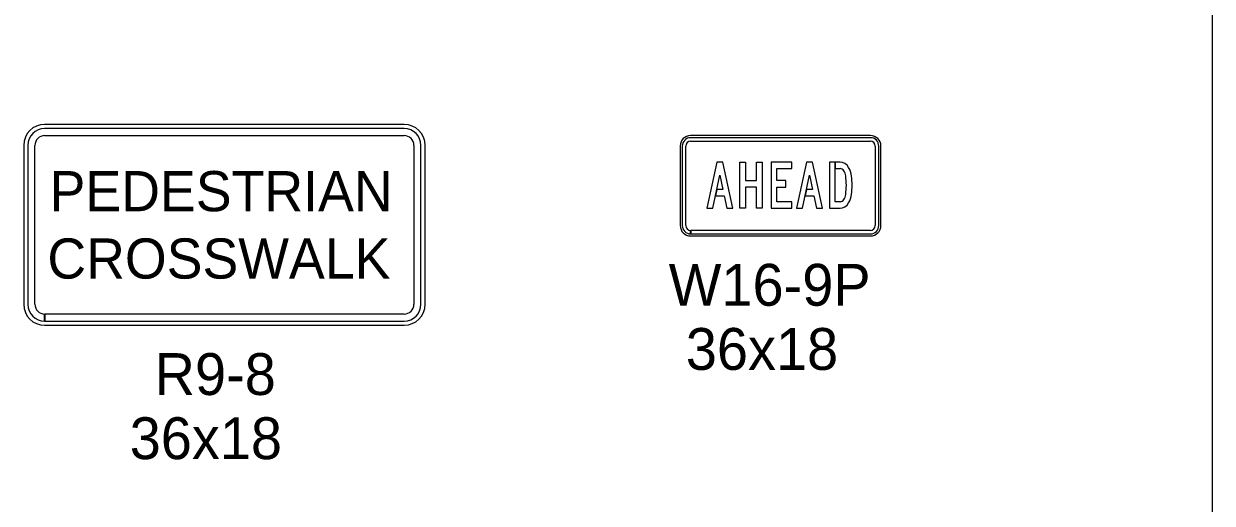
# Model space of a CAD drawing. Extents: x 1458 to 4498, y 17709 to 24109.
# Drawn here: x 2706.5 to 3132.7, y 20956.1 to 21127.9 of the extents above; entities that cross this region are included whole.
import ezdxf

# ---------------------------------------------------------------- set-up
doc = ezdxf.new("R2010")
doc.units = 0
for name, color, linetype in [('P_ODOT_PLAN_TBlock', 7, 'Continuous'), ('P_TRAF_SIGN_SignDetails', 7, 'Continuous'), ('P_TRAF_TCP_General', 7, 'Continuous')]:
    doc.layers.add(name, color=color, linetype=linetype)

msp = doc.modelspace()

# ---------------------------------------------------------------- linework, layer by layer
at = {"layer": 'P_ODOT_PLAN_TBlock'}
msp.add_line((3132.73, 21909.14), (3132.73, 20667.08), dxfattribs=at)
at = {"layer": 'P_TRAF_SIGN_SignDetails'}
for points in [[(2955.01, 21068.58), (2954.52, 21066.26), (2957.69, 21066.26), (2958.65, 21061.84), (2960.75, 21061.84), (2957.2, 21078.35), (2955.01, 21078.35), (2951.46, 21061.84), (2953.57, 21061.84), (2956.1, 21073.65), (2957.2, 21068.58)], [(2963.24, 21078.35), (2965.29, 21078.35), (2965.29, 21071.74), (2969.31, 21071.74), (2969.31, 21078.35), (2971.36, 21078.35), (2971.36, 21061.84), (2969.31, 21061.84), (2969.31, 21069.42), (2965.29, 21069.42), (2965.29, 21061.84), (2963.24, 21061.84)], [(2976.55, 21064.16), (2976.55, 21069.42), (2979.76, 21069.42), (2979.76, 21071.74), (2976.55, 21071.74), (2976.55, 21076.05), (2981.97, 21076.05), (2981.97, 21078.35), (2974.5, 21078.35), (2974.5, 21061.84), (2981.97, 21061.84), (2981.97, 21064.16)], [(2987.21, 21068.58), (2986.72, 21066.26), (2989.89, 21066.26), (2990.84, 21061.84), (2992.96, 21061.84), (2989.39, 21078.35), (2987.2, 21078.35), (2983.65, 21061.84), (2985.76, 21061.84), (2988.31, 21073.65), (2989.39, 21068.58)]]:
    msp.add_lwpolyline(points, close=True, dxfattribs=at)
for points in [[(2999.24, 21064.16), (2997.49, 21064.16), (2997.49, 21078.35), (2995.44, 21078.35), (2995.44, 21061.84), (2997.49, 21061.84), (2999.24, 21061.84)], [(2999.24, 21078.35), (2997.49, 21078.35), (2997.49, 21076.05), (2999.24, 21076.05)]]:
    msp.add_lwpolyline(points, dxfattribs=at)
for centre, major_axis, start_param, end_param in [((2999.34, 21074.42), (0, 3.93), 5.256629, 6.310275), ((2999.24, 21074.25), (0, 1.79), 5.295674, 6.281994), ((2998.12, 21072.94), (0, 3.58), 4.84938, 5.407144), ((2997.63, 21072.72), (0, 6.48), 4.80999, 5.326889), ((2979.08, 21069.68), (0, 25.32), 4.728786, 4.861202), ((2985.03, 21070.06), (0, 20.92), 4.713872, 4.870248), ((2998.12, 21067.24), (0, -3.58), 0.876041, 1.433806), ((2979.08, 21070.51), (0, -25.32), 1.421983, 1.554399), ((2997.63, 21067.47), (0, -6.48), 0.956296, 1.473195), ((2985.03, 21070.12), (0, -20.92), 1.412937, 1.569314), ((2999.24, 21065.94), (0, -1.79), 0.001192, 0.987511), ((2999.34, 21065.77), (0, -3.93), 6.256095, 7.309742)]:
    msp.add_ellipse(centre, major_axis=major_axis, ratio=0.88627, start_param=start_param, end_param=end_param, dxfattribs=at)
at = {"layer": 'P_TRAF_TCP_General'}
for p, q in [((2842.91, 21091.84), (2713.96, 21091.84)), ((2842.91, 21090.34), (2713.96, 21090.34)), ((2713.96, 21087.85), (2842.91, 21087.85)), ((3010.14, 21087.85), (2945.66, 21087.85)), ((2706.47, 21084.35), (2706.47, 21027.37)), ((2707.96, 21084.35), (2707.96, 21027.37)), ((2710.46, 21027.37), (2710.46, 21084.35)), ((2846.41, 21084.35), (2846.41, 21027.37)), ((2848.91, 21027.37), (2848.91, 21084.35)), ((2850.41, 21027.37), (2850.41, 21084.35)), ((2941.91, 21084.1), (2941.91, 21055.61)), ((2942.66, 21084.1), (2942.66, 21055.61)), ((2943.91, 21055.61), (2943.91, 21084.1)), ((3010.14, 21087.1), (2945.66, 21087.1)), ((2945.66, 21085.85), (3010.14, 21085.85)), ((3011.89, 21084.1), (3011.89, 21055.61)), ((3013.14, 21055.61), (3013.14, 21084.1)), ((3013.89, 21055.61), (3013.89, 21084.1)), ((2945.66, 21052.61), (2945.66, 21053.86)), ((3010.14, 21053.86), (2945.68, 21053.86)), ((2945.68, 21053.86), (2945.68, 21052.61)), ((2945.66, 21051.86), (3010.14, 21051.86)), ((2945.68, 21052.61), (3010.14, 21052.61)), ((2713.96, 21021.37), (2713.96, 21023.87)), ((2842.91, 21023.87), (2713.99, 21023.87)), ((2713.99, 21023.87), (2713.99, 21021.37)), ((2713.96, 21019.87), (2842.91, 21019.87)), ((2713.99, 21021.37), (2842.91, 21021.37))]:
    msp.add_line(p, q, dxfattribs=at)
for centre, radius, start, end in [((2713.96, 21084.35), 7.5, 90, 180), ((2842.91, 21084.35), 7.5, 0, 90), ((2713.96, 21084.35), 6, 90, 180), ((2713.96, 21084.35), 3.5, 90, 180), ((2842.91, 21084.35), 6, 0, 90), ((2842.91, 21084.35), 3.5, 0, 90), ((2945.66, 21084.1), 3.75, 90, 180), ((3010.14, 21084.1), 3.75, 0, 90), ((2945.66, 21084.1), 3, 90, 180), ((2945.66, 21084.1), 1.75, 90, 180), ((3010.14, 21084.1), 3, 0, 90), ((3010.14, 21084.1), 1.75, 0, 90), ((2945.66, 21055.61), 3.75, 180, 270), ((2945.66, 21055.61), 3, 180, 270), ((2945.66, 21055.61), 1.75, 180, 270), ((3010.14, 21055.61), 3, 270, 0), ((3010.14, 21055.61), 1.75, 270, 0), ((3010.14, 21055.61), 3.75, 270, 0), ((2713.96, 21027.37), 7.5, 180, 270), ((2713.96, 21027.37), 6, 180, 270), ((2713.96, 21027.37), 3.5, 180, 270), ((2842.91, 21027.37), 6, 270, 0), ((2842.91, 21027.37), 3.5, 270, 0), ((2842.91, 21027.37), 7.5, 270, 0)]:
    msp.add_arc(centre, radius, start, end, dxfattribs=at)

# ---------------------------------------------------------------- texts
for s, height, p in [('PEDESTRIAN', 14.4, (2715.73, 21060.73)), ('CROSSWALK', 14.4, (2714.93, 21036.59)), ('W16-9P', 14.994, (2937.78, 21026.87)), ('36x18', 14.994, (2943.93, 21003.88)), ('R9-8', 14.994, (2753.4, 20994.88)), ('36x18', 14.994, (2744.46, 20971.89))]:
    msp.add_text(s, height=height, dxfattribs=at).set_placement(p)

doc.saveas('drawing.dxf')
